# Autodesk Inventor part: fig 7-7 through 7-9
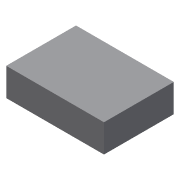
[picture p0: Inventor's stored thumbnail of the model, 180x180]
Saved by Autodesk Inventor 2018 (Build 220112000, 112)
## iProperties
Created: 2009-09
Part Number: fig 7-7 through 7-9
Document SubType Name: Modeling
Designer: Sham
Density: 1 g/cm^3
Material: Generic
Appearance: Default
Author: Sham
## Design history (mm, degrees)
sketch "Sketch1"
  geometry: L1 (-28, 20)-(0, 20); L2 (0, 20)-(0, 0); L3 (0, 0)-(-28, 0); L4 (-28, 0)-(-28, 20)
  constraints: 8 end point, 2 parallel, 1 horizontal, 1 perpendicular
extrude "Extrusion1" new body sketch "Sketch1" distance "d0" = 8; taper "d1" = 0 deg
body "Solid1"
